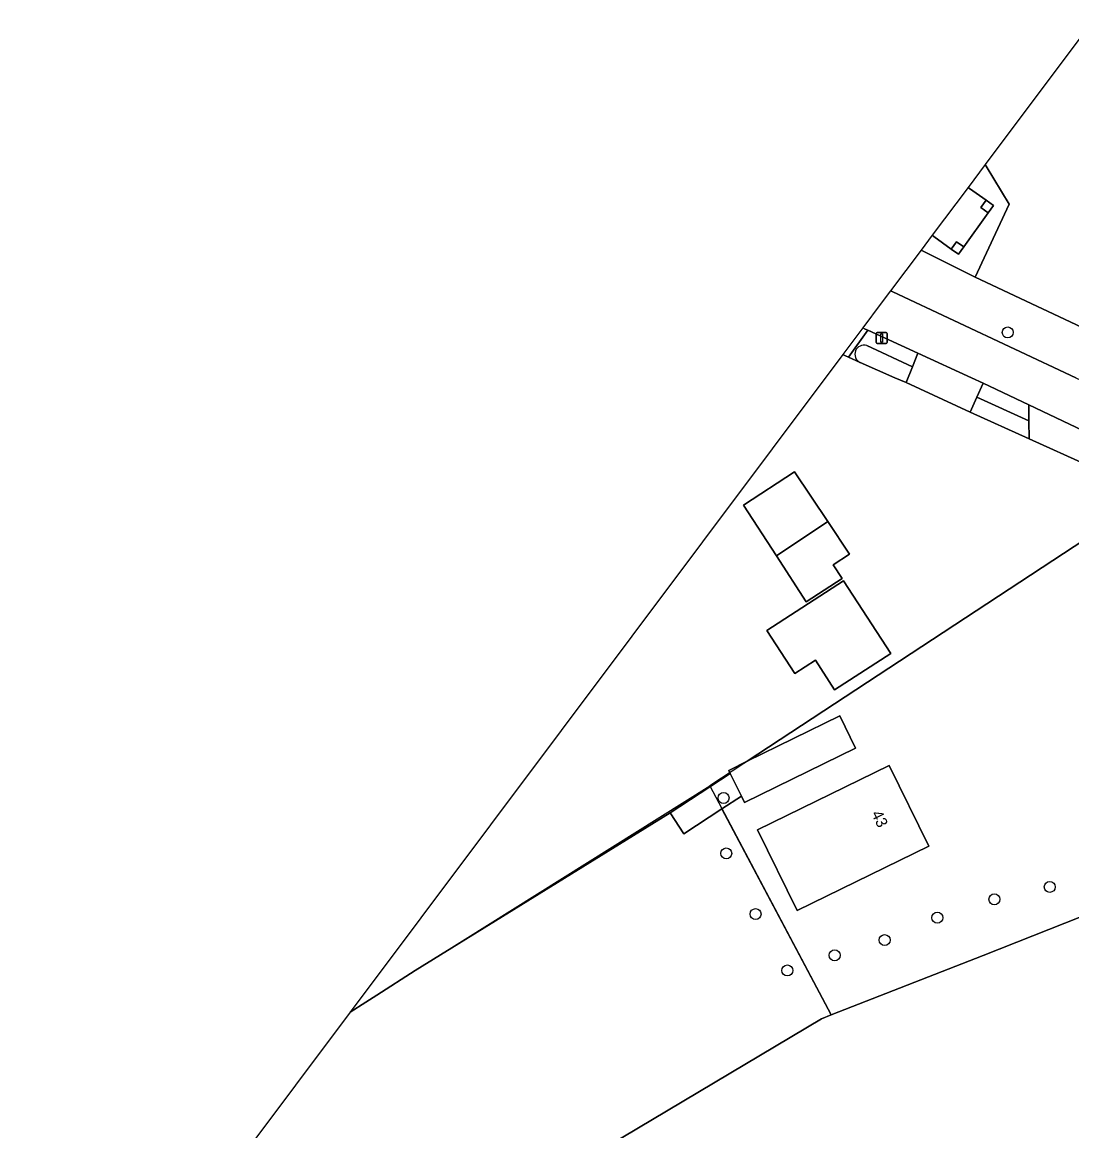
# Model space of a CAD drawing. Extents: x 159352 to 160617, y 385888 to 387323.
# Drawn here: x 159365.3 to 159458.5, y 386433.1 to 386531.6 of the extents above; entities that cross this region are included whole.
import ezdxf

# ---------------------------------------------------------------- set-up
doc = ezdxf.new("R2010")
doc.units = 0
for name, color, linetype in [('IMGEO_Boom', 7, 'Continuous'), ('IMGEO_Erf', 7, 'Continuous'), ('IMGEO_Fietspad_gesloten', 7, 'Continuous'), ('IMGEO_Gemengd_bos', 7, 'Continuous'), ('IMGEO_Grasland_overig', 7, 'Continuous'), ('IMGEO_Groenvoorziening', 7, 'Continuous'), ('IMGEO_Hek', 7, 'Continuous'), ('IMGEO_Hoogspanningsmast', 7, 'Continuous'), ('IMGEO_Lichtmast', 7, 'Continuous'), ('IMGEO_Pand', 7, 'Continuous'), ('IMGEO_Pand_nummerreeks', 7, 'Continuous'), ('IMGEO_Voetpad_open', 7, 'Continuous'), ('IMGEO_Waterloop', 7, 'Continuous')]:
    doc.layers.add(name, color=color, linetype=linetype)

msp = doc.modelspace()

# ---------------------------------------------------------------- linework, layer by layer
at = {"layer": 'IMGEO_Boom'}
for centre in [(159452.796, 386504.018), (159427.556, 386462.663), (159427.793, 386457.739), (159456.53, 386454.763), (159451.612, 386453.662), (159430.395, 386452.348), (159446.545, 386452.028), (159441.861, 386450.04), (159437.427, 386448.69), (159433.222, 386447.34)]:
    msp.add_circle(centre, 0.489, dxfattribs=at)
at = {"layer": 'IMGEO_Erf'}
msp.add_lwpolyline([(159438.145, 386502.052), (159394.408, 386443.649), (159395.776, 386444.526), (159396.765, 386445.16), (159400.178, 386447.348), (159422.814, 386461.343), (159428.157, 386464.835), (159428.019, 386465.117), (159429.657, 386465.92), (159465.501, 386489.478), (159466.443, 386489.251), (159459.951, 386492.191), (159454.7, 386494.569), (159449.452, 386496.945), (159443.774, 386499.56), (159442.776, 386500), (159439.685, 386501.364), (159438.638, 386501.832), (159438.384, 386501.945), (159438.145, 386502.052), (159438.145, 386502.052)], dxfattribs=at)
for points in [[(159432.244, 386484.166), (159429.317, 386488.675), (159433.867, 386491.63), (159436.813, 386487.216), (159438.738, 386484.33), (159437.287, 386483.388), (159438.079, 386482.167), (159434.888, 386480.095)], [(159438.214, 386481.96), (159442.402, 386475.511), (159437.42, 386472.276), (159435.707, 386474.915), (159433.888, 386473.733), (159431.413, 386477.544)]]:
    msp.add_lwpolyline(points, close=True, dxfattribs=at)
at = {"layer": 'IMGEO_Fietspad_gesloten'}
for points in [[(159458.854, 386500), (159442.597, 386507.622), (159442.389, 386507.72), (159441.564, 386506.618), (159439.918, 386504.42)], [(159439.918, 386504.42), (159439.918, 386504.42), (159440.144, 386504.317), (159440.37, 386504.214), (159444.817, 386502.181), (159449.586, 386500), (159450.625, 386499.508), (159454.66, 386497.595), (159460.09, 386495.022)]]:
    msp.add_lwpolyline(points, dxfattribs=at)
at = {"layer": 'IMGEO_Gemengd_bos'}
msp.add_lwpolyline([(159460.26, 386531.583), (159450.795, 386518.945), (159450.889, 386518.789), (159452.935, 386515.403), (159449.895, 386508.936), (159467.828, 386500.498)], dxfattribs=at)
at = {"layer": 'IMGEO_Grasland_overig'}
msp.add_lwpolyline([(159446.082, 386512.651), (159446.082, 386512.651), (159446.243, 386512.535), (159447.766, 386511.433), (159448.235, 386512.081), (159448.88, 386511.614), (159451.053, 386514.644), (159450.403, 386515.11), (159450.868, 386515.759), (159449.411, 386516.8), (159449.266, 386516.903)], close=True, dxfattribs=at)
at = {"layer": 'IMGEO_Groenvoorziening'}
for points in [[(159450.795, 386518.945), (159449.266, 386516.903), (159449.411, 386516.8), (159450.868, 386515.759), (159451.519, 386515.294), (159451.053, 386514.644), (159448.88, 386511.614), (159448.414, 386510.964), (159447.766, 386511.433), (159446.243, 386512.535), (159446.082, 386512.651), (159446.082, 386512.651), (159445.095, 386511.333), (159445.095, 386511.333), (159445.282, 386511.24), (159449.895, 386508.936), (159452.935, 386515.403), (159450.889, 386518.789)], [(159442.389, 386507.72), (159442.597, 386507.622), (159458.854, 386500), (159467.828, 386495.766), (159467.828, 386500.498), (159449.895, 386508.936), (159445.282, 386511.24), (159445.095, 386511.333), (159445.095, 386511.333)], [(159450.625, 386499.508), (159450.061, 386498.275), (159454.679, 386496.16), (159454.66, 386497.595)], [(159468.819, 386484.003), (159468.978, 386484.923), (159468.942, 386485.857), (159468.528, 386487.192), (159467.722, 386488.334), (159467.005, 386488.931), (159466.443, 386489.251), (159465.501, 386489.478), (159429.657, 386465.92), (159437.872, 386469.949), (159439.272, 386467.094), (159429.419, 386462.262), (159429.146, 386462.818), (159427.415, 386461.686), (159437.125, 386443.389), (159450.601, 386448.684), (159460.866, 386452.718), (159460.504, 386454.825), (159460.775, 386457.568)], [(159445.777, 386458.379), (159434.105, 386452.655), (159430.582, 386459.838), (159442.254, 386465.562)], [(159365.266, 386404.735), (159365.71, 386404.009), (159382.354, 386376.783), (159407.698, 386393.628), (159393.962, 386414.948), (159392.607, 386417.051), (159436.243, 386443.042), (159437.125, 386443.389), (159427.415, 386461.686), (159424.034, 386459.476), (159422.814, 386461.343), (159400.178, 386447.348), (159396.765, 386445.16), (159395.776, 386444.526), (159394.408, 386443.649)]]:
    msp.add_lwpolyline(points, close=True, dxfattribs=at)
for points in [[(159440.37, 386504.214), (159438.638, 386501.832), (159439.685, 386501.364)], [(159440.271, 386502.85), (159444.331, 386500.961), (159444.817, 386502.181), (159440.37, 386504.214)], [(159469.384, 386427.253), (159474.123, 386431.798), (159464.607, 386446.619), (159463.993, 386447.575), (159460.866, 386452.718), (159450.601, 386448.684), (159437.125, 386443.389), (159436.243, 386443.042), (159392.607, 386417.051), (159393.962, 386414.948), (159407.698, 386393.628), (159382.354, 386376.783), (159419.283, 386316.377), (159458.061, 386254.291), (159460.741, 386250), (159500, 386186.48), (159520.962, 386153.341), (159520.51, 386153.027), (159521.879, 386150.588), (159523.149, 386152.545), (159524.56, 386155.081), (159530.909, 386143.925)]]:
    msp.add_lwpolyline(points, dxfattribs=at)
msp.add_arc((159440.019, 386502.091), 0.8, 71.6537, 245.30298, dxfattribs=at)
at = {"layer": 'IMGEO_Hek'}
for points in [[(159449.895, 386508.936), (159452.935, 386515.403), (159450.889, 386518.789)], [(159450.889, 386518.789), (159450.795, 386518.945)], [(159467.828, 386500.498), (159449.895, 386508.936)], [(159466.443, 386489.251), (159465.501, 386489.478), (159426.329, 386463.733)], [(159395.776, 386444.526), (159396.765, 386445.16), (159400.178, 386447.348), (159426.329, 386463.733)], [(159426.329, 386463.733), (159437.125, 386443.389)], [(159450.601, 386448.684), (159437.125, 386443.389)], [(159394.408, 386443.649), (159395.776, 386444.526)], [(159393.962, 386414.948), (159392.607, 386417.051), (159436.243, 386443.042), (159437.125, 386443.389)]]:
    msp.add_lwpolyline(points, dxfattribs=at)
at = {"layer": 'IMGEO_Hoogspanningsmast'}
for points in [[(159451.519, 386515.294), (159450.868, 386515.759), (159450.403, 386515.11), (159451.053, 386514.644)], [(159448.88, 386511.614), (159448.235, 386512.081), (159447.766, 386511.433), (159448.414, 386510.964)]]:
    msp.add_lwpolyline(points, close=True, dxfattribs=at)
at = {"layer": 'IMGEO_Lichtmast'}
for p, q in [((159441.199, 386504.028), (159441.989, 386504.028)), ((159441.989, 386504.028), (159441.199, 386504.028)), ((159441.099, 386503.128), (159441.099, 386503.928)), ((159441.099, 386503.928), (159441.099, 386503.128)), ((159441.989, 386503.028), (159441.199, 386503.028)), ((159441.199, 386503.028), (159441.989, 386503.028)), ((159442.089, 386503.928), (159442.089, 386503.128)), ((159442.089, 386503.128), (159442.089, 386503.928))]:
    msp.add_line(p, q, dxfattribs=at)
msp.add_lwpolyline([(159441.519, 386503.903), (159441.669, 386503.903), (159441.669, 386503.153), (159441.519, 386503.153), (159441.519, 386503.903)], dxfattribs=at)
for centre, start, end in [((159441.199, 386503.928), 90, 180), ((159441.199, 386503.928), 90, 180), ((159441.989, 386503.928), 0, 90), ((159441.989, 386503.928), 360, 90), ((159441.199, 386503.128), 180, 270), ((159441.199, 386503.128), 180, 270), ((159441.989, 386503.128), 270, 0), ((159441.989, 386503.128), 270, 0)]:
    msp.add_arc(centre, 0.1, start, end, dxfattribs=at)
at = {"layer": 'IMGEO_Pand'}
for points in [[(159432.244, 386484.166), (159436.813, 386487.216), (159433.867, 386491.63), (159429.317, 386488.675)], [(159436.813, 386487.216), (159432.244, 386484.166), (159434.888, 386480.095), (159438.079, 386482.167), (159437.287, 386483.388), (159438.738, 386484.33)], [(159437.42, 386472.276), (159442.402, 386475.511), (159438.214, 386481.96), (159431.413, 386477.544), (159433.888, 386473.733), (159435.707, 386474.915)], [(159429.657, 386465.92), (159428.019, 386465.117), (159428.157, 386464.835), (159429.146, 386462.818), (159429.419, 386462.262), (159439.272, 386467.094), (159437.872, 386469.949)], [(159430.582, 386459.838), (159434.105, 386452.655), (159445.777, 386458.379), (159442.254, 386465.562)], [(159429.146, 386462.818), (159428.157, 386464.835), (159422.814, 386461.343), (159424.034, 386459.476), (159427.415, 386461.686)]]:
    msp.add_lwpolyline(points, close=True, dxfattribs=at)
at = {"layer": 'IMGEO_Voetpad_open'}
for points in [[(159438.145, 386502.052), (159438.145, 386502.052), (159438.384, 386501.945), (159438.638, 386501.832), (159440.37, 386504.214), (159440.144, 386504.317), (159439.918, 386504.42), (159439.918, 386504.42)], [(159449.452, 386496.945), (159450.061, 386498.275), (159450.625, 386499.508), (159449.586, 386500), (159444.817, 386502.181), (159444.331, 386500.961), (159443.774, 386499.56)], [(159459.951, 386492.191), (159460.067, 386493.693), (159460.082, 386493.883), (159460.09, 386495.022), (159454.66, 386497.595), (159454.679, 386496.16), (159454.7, 386494.569)]]:
    msp.add_lwpolyline(points, close=True, dxfattribs=at)
at = {"layer": 'IMGEO_Waterloop'}
msp.add_lwpolyline([(159439.685, 386501.364), (159442.776, 386500), (159443.774, 386499.56), (159444.331, 386500.961), (159440.271, 386502.85)], dxfattribs=at)
msp.add_lwpolyline([(159454.679, 386496.16), (159450.061, 386498.275), (159449.452, 386496.945), (159454.7, 386494.569)], close=True, dxfattribs=at)
msp.add_arc((159440.019, 386502.091), 0.8, 71.6537, 245.30298, dxfattribs=at)

# ---------------------------------------------------------------- texts
at = {"layer": 'IMGEO_Pand_nummerreeks'}
msp.add_text('43', height=1, rotation=295.99149, dxfattribs=at).set_placement((159440.656, 386461.27))

doc.saveas('drawing.dxf')
